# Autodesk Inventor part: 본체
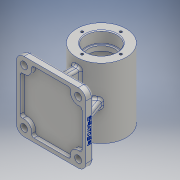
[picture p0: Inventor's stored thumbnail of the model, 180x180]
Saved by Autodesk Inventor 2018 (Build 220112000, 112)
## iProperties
Created: 2019-06
Part Number: 본체
Material: 알루미늄 6061
Document SubType Name: Modeling
Designer: Administrator
Density: 2.7 g/cm^3
Appearance: 알루미늄 - 평지
Author: Administrator
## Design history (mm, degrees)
sketch "스케치1"
  geometry: C1 r 32 at (0, 0); 1 further point
  constraints: 1 centre point, 1 coincident
  dimensions: "d0" = 64 diameter of C1
extrude "돌출1" new body sketch "스케치1" stored distance "d1" = 90; taper "d2" = 0 deg
sketch "스케치2"
  geometry: L1 (0, 0)-(0, -65); L2 (0, -65)-(45, -65); L3 (45, -65)-(45, -55); L4 (45, -55)-(-45, -55); L5 (-45, -55)-(-45, -65); L6 (-45, -65)-(0, -65)
  constraints: 12 end point, 4 perpendicular, 1 point on line, 1 vertical
  dimensions: "d3" = 65 distance of L1.start L1.end; "d4" = 45 distance of L1.end L2.end; "d5" = 10 distance of L2.end L3.end; "d6" = 90 distance of L3.end L4.end; "d7" = 10 distance of L4.end L5.end
extrude "돌출2" join sketch "스케치2" stored distance "d8" = 90; taper "d9" = 0 deg
sketch "스케치3"
  geometry: L1 (45, 45)-(50, 45); L2 (50, 45)-(50, 80); L3 (50, 80)-(40, 80); L4 (40, 80)-(40, 10); L5 (40, 10)-(50, 10); L6 (50, 10)-(50, 45)
  constraints: 12 end point, 3 perpendicular, 1 horizontal, 1 point on line
  dimensions: "d10" = 5 distance of L1.start L1.end; "d11" = 35 distance of L1.end L2.end; "d12" = 10 distance of L2.end L3.end; "d13" = 70 distance of L3.end L4.end; "d14" = 10 distance of L4.end L5.end
extrude "돌출3" join sketch "스케치3" stored distance "d15" = 90; taper "d16" = 0 deg
sketch "스케치4"
  geometry: L1 (-35, -55)-(-23.058, -22.189); L2 (-35, -55)-(-5, -55); 3 further points
  constraints: 4 end point, 1 horizontal
  dimensions: "d17" = 10 distance of point (-45, -55) L1.start
feature "리브1" sketch "스케치4" dims "d19" = 1, "d20" = 10, "d21" = 0, "d22" = 0, "d23" = 1, "d24" = 1
fillet "모깎기1" dims "d25" = 3
fillet "모깎기2" dims "d26" = 10
fillet "모깎기3" dims "d27" = 3
sketch "스케치5"
  geometry: A1 r 10 centre (0, 77) between (0, 87) and (-10, 77) reference; A2 r 7 centre (70, 77) between (77, 77) and (70, 84) reference; A3 r 7 centre (70, 7) between (70, 0) and (77, 7) reference; A4 r 7 centre (0, 7) between (-7, 7) and (0, 0) reference; 5 further points
  constraints: 4 coincident
hole "구멍1" sketch "스케치5" at (0, 77), (70, 77), (70, 7), (0, 7) diameter "d28" = 9; stored, may be unused: countersink angle "d32" = 90 deg, drill point angle "d34" = 118 deg; dims "d29" = 6, "d30" = 4, "d31" = 2, "d33" = 8
sketch "스케치6"
  geometry: C1 r 20 at (0, 0); 1 further point
  constraints: 1 centre point, 1 coincident
  dimensions: "d35" = 40 diameter of C1
extrude "돌출4" cut sketch "스케치6" distance "d36" = 15; taper "d37" = 0 deg
sketch "스케치7"
  geometry: C1 r 17 at (0, 0); 1 further point
  constraints: 1 centre point, 1 coincident
  dimensions: "d38" = 34 diameter of C1
extrude "돌출5" cut sketch "스케치7" distance "d39" = 6; taper "d40" = 0 deg
sketch "스케치8"
  geometry: C1 r 25 at (0, 0); 1 further point
  constraints: 1 centre point, 1 coincident
  dimensions: "d41" = 50 diameter of C1
extrude "돌출6" cut sketch "스케치8" distance "d42" = 24; taper "d43" = 0 deg
chamfer "모따기1" distance "d44" = 1; stored, may be unused: second distance "d45" = 2, angle "d46" = 45 deg
fillet "모깎기4" dims "d47" = 0.6
fillet "모깎기5" dims "d48" = 3
sketch "스케치9"
  geometry: C1 r 25 at (0, 0); A1 r 25 centre (0, 0) between (0, 25) and (25, 0) reference; 3 further points
  constraints: 4 point on circle, 1 centre point, 1 coincident
  dimensions: "d49" = 50 diameter of C1
hole "구멍2" sketch "스케치9" at (0, 25), (25, 0), (0, -25), (-25, 0) diameter "d50" = 3.242; stored, may be unused: countersink angle "d54" = 90 deg, drill point angle "d56" = 118 deg; dims "d51" = 7, "d52" = 4, "d53" = 2, "d55" = 9
node "작업 평면1"
sketch "스케치10"
  geometry: C1 r 5 at (0, 0); 1 further point
  constraints: 1 centre point, 1 coincident
  dimensions: "d57" = 10 diameter of C1
extrude "돌출7" join sketch "스케치10" distance "d58" = 3; taper "d60" = 0 deg; dims "d59" = 1, "d61" = 0
sketch "스케치11"
  geometry: C1 r 5 at (0, 0) reference; 2 further points
  constraints: 1 coincident
hole "구멍3" sketch "스케치11" at (0, 0) diameter "d62" = 4.917; stored, may be unused: countersink angle "d66" = 90 deg, drill point angle "d68" = 118 deg; dims "d63" = 12, "d64" = 4, "d65" = 2, "d67" = 17.1
fillet "모깎기6" dims "d69" = 2
sketch "스케치12"
  geometry: L1 (70, 0)-(0, 0) reference; L2 (-10, 7)-(-10, 0) reference; 2 further points
  constraints: 1 other
  dimensions: "d70" = 4 distance from line of L1 point (35, 4); "d71" = 45 distance from line of L2 point (35, 4)
feature "엠보싱1" sketch "스케치12" dims "d2" = 0, "d72" = 0.5, "d73" = 0
sketch "스케치13"
  geometry: L1 (12.845, 85)-(57.155, 85); L2 (75, 67.155)-(75, 22.845); L3 (57.155, 5)-(12.845, 5); L4 (-5, 22.845)-(-5, 67.155); L5 (-5, 85)-(75, 5); L6 (75, 85)-(-5, 5); C1 r 4.5 at (70, 80) reference; C2 r 4.5 at (70, 10) reference; C3 r 4.5 at (0, 10) reference; C4 r 4.5 at (0, 80) reference; C5 r 2.458 at (35, 45) reference; A1 r 10 centre (70, 80) between (60.119, 81.538) and (71.538, 70.119); A2 r 10 centre (70, 10) between (71.538, 19.881) and (60.119, 8.462); A3 r 10 centre (0, 10) between (9.881, 8.462) and (-1.538, 19.881); A4 r 10 centre (0, 80) between (-1.538, 70.119) and (9.881, 81.538); A5 r 3 centre (72, 67.155) between (75, 67.155) and (71.538, 70.119); A6 r 3 centre (57.155, 82) between (60.119, 81.538) and (57.155, 85); A7 r 3 centre (12.845, 82) between (12.845, 85) and (9.881, 81.538); A8 r 3 centre (-2, 67.155) between (-1.538, 70.119) and (-5, 67.155); A9 r 3 centre (-2, 22.845) between (-5, 22.845) and (-1.538, 19.881); A10 r 3 centre (12.845, 8) between (9.881, 8.462) and (12.845, 5); A11 r 3 centre (57.155, 8) between (57.155, 5) and (60.119, 8.462); A12 r 3 centre (72, 22.845) between (71.538, 19.881) and (75, 22.845); 9 further points
  constraints: 32 point on circle, 16 tangent, 12 centre point, 12 end point, 8 point on line, 7 equal radius, 4 coincident, 2 midpoint, 2 parallel, 1 horizontal, 1 perpendicular
  dimensions: "d74" = 20 diameter of A1; "d75" = 80 distance of L5.end L6.end; "d76" = 80 distance of L6.start L5.end; "d77" = 3 radius of A5
extrude "돌출8" cut sketch "스케치13" distance "d78" = 5; taper "d79" = 0 deg
sketch "스케치14"
  geometry: C1 r 2.458 at (0, 0) reference; C2 r 2.458 at (0, 0); 1 further point
  constraints: 1 centre point, 1 coincident
extrude "돌출9" cut sketch "스케치14" distance "d80" = 5; taper "d81" = 0 deg
node "솔리드1"
mirror "미러1"
mirror "미러2"
mirror "미러3"
